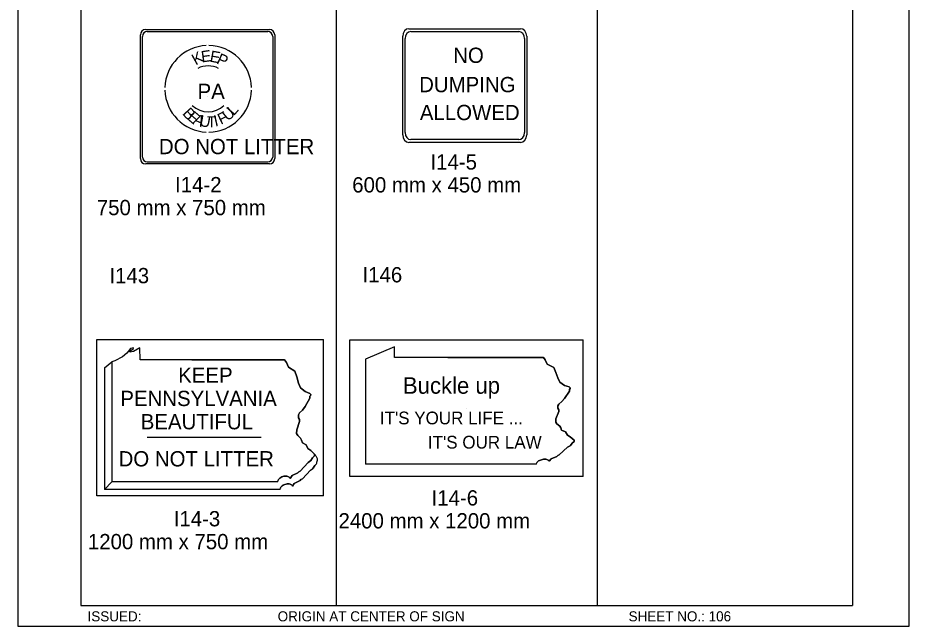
# Model space of a CAD drawing. Extents: x -12 to 6962, y -3756 to 679.
# Drawn here: x 4896 to 5071.3, y -234.4 to -114.9 of the extents above; entities that cross this region are included whole.
import ezdxf

# ---------------------------------------------------------------- set-up
doc = ezdxf.new("R2010")
doc.units = 0
for name, color, linetype in [('Level 1', 7, 'Continuous'), ('Level 2', 7, 'Continuous'), ('Level 3', 7, 'Continuous'), ('Level 61', 7, 'Continuous')]:
    doc.layers.add(name, color=color, linetype=linetype)

msp = doc.modelspace()

# ---------------------------------------------------------------- linework, layer by layer
at = {"layer": 'Level 1'}
for p, q in [((4908.37, -30.35), (4908.37, -230.35)), ((4958.6, -30.35), (4958.6, -230.35)), ((5009.89, -30.35), (5009.89, -230.35)), ((5060.12, -30.35), (5060.12, -230.35)), ((4921.15, -117.2), (4945.45, -117.2)), ((4972.9, -117.04), (4994.85, -117.04)), ((4920.09, -142.56), (4920.09, -118.26)), ((4920.48, -142.25), (4920.48, -118.57)), ((4921.46, -117.6), (4945.13, -117.6)), ((4946.11, -118.57), (4946.11, -142.25)), ((4946.5, -118.26), (4946.5, -142.56)), ((4971.69, -137.91), (4971.69, -118.53)), ((4972.15, -137.46), (4972.15, -118.97)), ((4973.27, -117.6), (4994.49, -117.6)), ((4995.62, -118.97), (4995.62, -137.46)), ((4996.07, -118.53), (4996.07, -137.91)), ((4933.3, -130.41), (4933.3, -130.41)), ((4994.85, -139.4), (4972.9, -139.4)), ((4994.49, -138.84), (4973.27, -138.84)), ((4945.45, -143.62), (4921.15, -143.62)), ((4945.13, -143.23), (4921.46, -143.23)), ((4911.53, -208.85), (4911.53, -178.09)), ((4911.53, -178.09), (4956.07, -178.09)), ((4956.07, -208.85), (4956.07, -178.09)), ((4961.31, -205.05), (4961.31, -178.16)), ((4961.31, -178.16), (5007.18, -178.16)), ((5007.18, -205.05), (5007.18, -178.16)), ((4970.05, -179.57), (4964.38, -181.98)), ((4970.05, -181.67), (4970.05, -179.57)), ((4913.02, -183.66), (4914.51, -182.46)), ((4984.24, -191.61), (4984.24, -191.61)), ((4933.8, -193.47), (4933.8, -193.47)), ((4921.41, -197.28), (4943.85, -197.28)), ((5002.47, -200.77), (5004.1, -199.28)), ((4951.5, -203.96), (4953.08, -202.25)), ((4998, -202.6), (4964.37, -202.6)), ((4998, -202.6), (4964.37, -202.6)), ((4998, -202.6), (4998.03, -202.34)), ((4998, -202.6), (4998.03, -202.34)), ((4998, -202.6), (4998.03, -202.34)), ((4951.94, -205.48), (4953.52, -203.78)), ((5007.18, -205.05), (4961.31, -205.05)), ((4914.51, -206.06), (4913.01, -207.55)), ((4947.15, -206.04), (4914.51, -206.04)), ((4947.15, -206.04), (4914.51, -206.04)), ((4947.15, -206.04), (4947.18, -205.75)), ((4947.15, -206.04), (4947.18, -205.75)), ((4947.15, -206.04), (4947.18, -205.75)), ((4947.6, -207.57), (4913.01, -207.57)), ((4947.6, -207.57), (4914.95, -207.57)), ((4947.6, -207.57), (4914.95, -207.57)), ((4947.6, -207.57), (4947.62, -207.27)), ((4947.6, -207.57), (4947.62, -207.27)), ((4947.6, -207.57), (4947.62, -207.27)), ((4956.07, -208.85), (4911.53, -208.85)), ((4908.37, -230.35), (5060.12, -230.35))]:
    msp.add_line(p, q, dxfattribs=at)
for points in [[(4930.23, -182.1), (4920.02, -182.1), (4920.01, -179.71), (4918.73, -180.43), (4918.01, -180.62), (4918.19, -180.25), (4918.73, -179.88), (4918.74, -179.71), (4918.18, -179.88), (4917.45, -180.79), (4916.55, -181.53), (4915.06, -182.28), (4914.51, -182.46)], [(4953.08, -202.25), (4953.59, -201.9), (4953.97, -201.34), (4954.32, -200.98), (4954.33, -200.63), (4953.58, -199.88), (4953.03, -199.52), (4952.68, -198.8), (4951.94, -198.42), (4951.76, -197.86), (4951.57, -197.5), (4951.03, -196.97), (4950.82, -196.58), (4950.84, -195.86), (4951.39, -194.19), (4951.38, -193.83), (4951.2, -193.47), (4951.21, -192.92), (4951.2, -192.93), (4951.39, -192.54), (4951.95, -191.98), (4952.49, -191.26), (4953.41, -189.61), (4953.4, -189.6), (4953.41, -189.24), (4953.59, -189.06), (4953.59, -188.88), (4953.4, -188.69), (4952.49, -188.33), (4951.57, -187.59), (4951.21, -186.66), (4950.85, -185.43), (4950.47, -184.3), (4949.19, -183.55), (4948.81, -182.63), (4948.45, -182.1), (4930.23, -182.1)], [(4953.08, -202.25), (4953.59, -201.9), (4953.97, -201.34), (4954.32, -200.98), (4954.33, -200.63), (4953.58, -199.88), (4953.03, -199.52), (4952.68, -198.8), (4951.94, -198.42), (4951.76, -197.86), (4951.57, -197.5), (4951.03, -196.97), (4950.82, -196.58), (4950.84, -195.86), (4951.39, -194.19), (4951.38, -193.83), (4951.2, -193.47), (4951.21, -192.92), (4951.2, -192.93), (4951.39, -192.54), (4951.95, -191.98), (4952.49, -191.26), (4953.41, -189.61), (4953.4, -189.6), (4953.41, -189.24), (4953.59, -189.06), (4953.59, -188.88), (4953.4, -188.69), (4952.49, -188.33), (4951.57, -187.59), (4951.21, -186.66), (4950.85, -185.43), (4950.47, -184.3), (4949.19, -183.55), (4948.81, -182.63), (4948.45, -182.1), (4930.23, -182.1)], [(4930.23, -182.1), (4948.45, -182.1), (4948.81, -182.63), (4949.19, -183.55), (4950.47, -184.3), (4950.85, -185.43), (4951.21, -186.66), (4951.57, -187.59), (4952.49, -188.33), (4953.4, -188.69), (4953.59, -188.88), (4953.59, -189.06), (4953.41, -189.24), (4953.4, -189.6), (4953.41, -189.61), (4952.49, -191.26), (4951.95, -191.98), (4951.39, -192.54), (4951.2, -192.93), (4951.21, -192.92), (4951.2, -193.47), (4951.38, -193.83), (4951.39, -194.19), (4950.84, -195.86), (4950.82, -196.58), (4951.03, -196.97), (4951.57, -197.5), (4951.76, -197.86), (4951.94, -198.42), (4952.68, -198.8), (4953.03, -199.52), (4953.58, -199.88), (4954.33, -200.63), (4954.32, -200.98), (4953.97, -201.34), (4953.62, -201.86)], [(4964.38, -181.98), (4964.37, -202.6)], [(5004.1, -199.28), (5004.63, -198.98), (5005.02, -198.49), (5005.38, -198.17), (5005.39, -197.86), (5004.62, -197.21), (5004.05, -196.9), (5003.69, -196.27), (5002.92, -195.93), (5002.74, -195.44), (5002.55, -195.13), (5001.99, -194.67), (5001.78, -194.33), (5001.79, -193.69), (5002.36, -192.24), (5002.35, -191.92), (5002.17, -191.6), (5002.17, -191.13), (5002.17, -191.13), (5002.36, -190.8), (5002.94, -190.31), (5003.5, -189.67), (5004.44, -188.23), (5004.44, -188.22), (5004.44, -187.91), (5004.63, -187.75), (5004.62, -187.6), (5004.43, -187.43), (5003.5, -187.11), (5002.55, -186.47), (5002.17, -185.66), (5001.81, -184.58), (5001.41, -183.59), (5000.09, -182.94), (4999.7, -182.12), (4999.34, -181.66), (4970.05, -181.67)], [(5004.1, -199.28), (5004.63, -198.98), (5005.02, -198.49), (5005.38, -198.17), (5005.39, -197.86), (5004.62, -197.21), (5004.05, -196.9), (5003.69, -196.27), (5002.92, -195.93), (5002.74, -195.44), (5002.55, -195.13), (5001.99, -194.67), (5001.78, -194.33), (5001.79, -193.69), (5002.36, -192.24), (5002.35, -191.92), (5002.17, -191.6), (5002.17, -191.13), (5002.17, -191.13), (5002.36, -190.8), (5002.94, -190.31), (5003.5, -189.67), (5004.44, -188.23), (5004.44, -188.22), (5004.44, -187.91), (5004.63, -187.75), (5004.62, -187.6), (5004.43, -187.43), (5003.5, -187.11), (5002.55, -186.47), (5002.17, -185.66), (5001.81, -184.58), (5001.41, -183.59), (5000.09, -182.94), (4999.7, -182.12), (4999.34, -181.66), (4980.57, -181.67)], [(4980.57, -181.67), (4999.34, -181.66), (4999.7, -182.12), (5000.09, -182.94), (5001.41, -183.59), (5001.81, -184.58), (5002.17, -185.66), (5002.55, -186.47), (5003.5, -187.11), (5004.43, -187.43), (5004.62, -187.6), (5004.63, -187.75), (5004.44, -187.91), (5004.44, -188.22), (5004.44, -188.23), (5003.5, -189.67), (5002.94, -190.31), (5002.36, -190.8), (5002.17, -191.13), (5002.17, -191.13), (5002.17, -191.6), (5002.35, -191.92), (5002.36, -192.24), (5001.79, -193.69), (5001.78, -194.33), (5001.99, -194.67), (5002.55, -195.13), (5002.74, -195.44), (5002.92, -195.93), (5003.69, -196.27), (5004.05, -196.9), (5004.62, -197.21), (5005.39, -197.86), (5005.38, -198.17), (5005.02, -198.49), (5004.65, -198.94)], [(4913.02, -183.66), (4913.01, -207.55)], [(4914.51, -182.46), (4914.51, -206.04)], [(5004.65, -198.94), (5004.63, -198.98), (5004.1, -199.28)], [(4998.02, -202.36), (4998.03, -202.34), (4998.13, -202.2), (4998.24, -202.08), (4998.39, -201.97), (4998.59, -201.86), (4998.76, -201.78), (4998.95, -201.72), (4999.17, -201.67), (4999.39, -201.64), (4999.62, -201.63), (4999.82, -201.64), (5000.01, -201.68), (5000.16, -201.74), (5000.27, -201.8), (5000.39, -201.9), (5000.47, -202.02), (5000.85, -201.55), (5001.99, -201.06), (5002.18, -200.9), (5002.47, -200.77)], [(5002.47, -200.77), (5002.18, -200.9), (5001.99, -201.06), (5000.85, -201.55), (5000.47, -202.02), (5000.39, -201.9), (5000.27, -201.8), (5000.16, -201.74), (5000.01, -201.68), (4999.82, -201.64), (4999.62, -201.63), (4999.39, -201.64), (4999.17, -201.67), (4998.95, -201.72), (4998.76, -201.78), (4998.59, -201.86), (4998.39, -201.97), (4998.24, -202.08), (4998.13, -202.2), (4998.03, -202.34), (4998.02, -202.36)], [(4998.02, -202.36), (4998.03, -202.34), (4998.13, -202.2), (4998.24, -202.08), (4998.39, -201.97), (4998.59, -201.86), (4998.76, -201.78), (4998.95, -201.72), (4999.17, -201.67), (4999.39, -201.64), (4999.62, -201.63), (4999.82, -201.64), (5000.01, -201.68), (5000.16, -201.74), (5000.27, -201.8), (5000.39, -201.9), (5000.47, -202.02), (5000.85, -201.55), (5001.99, -201.06), (5002.18, -200.9), (5002.47, -200.77)], [(4953.62, -201.86), (4953.59, -201.9), (4953.08, -202.25)], [(4953.52, -203.78), (4954.03, -203.42), (4954.41, -202.87), (4954.72, -202.55)], [(4954.4, -202.88), (4954.06, -203.39)], [(4954.58, -202.69), (4954.41, -202.87), (4954.4, -202.88)], [(4954.72, -202.55), (4954.58, -202.69)], [(4947.18, -205.77), (4947.18, -205.75), (4947.28, -205.59), (4947.39, -205.46), (4947.53, -205.33), (4947.73, -205.2), (4947.89, -205.11), (4948.08, -205.04), (4948.29, -204.98), (4948.51, -204.95), (4948.73, -204.94), (4948.92, -204.95), (4949.1, -204.99), (4949.25, -205.06), (4949.36, -205.13), (4949.48, -205.25), (4949.56, -205.39), (4949.92, -204.85), (4951.03, -204.29), (4951.22, -204.1), (4951.5, -203.96)], [(4951.5, -203.96), (4951.22, -204.1), (4951.03, -204.29), (4949.92, -204.85), (4949.56, -205.39), (4949.48, -205.25), (4949.36, -205.13), (4949.25, -205.06), (4949.1, -204.99), (4948.92, -204.95), (4948.73, -204.94), (4948.51, -204.95), (4948.29, -204.98), (4948.08, -205.04), (4947.89, -205.11), (4947.73, -205.2), (4947.53, -205.33), (4947.39, -205.46), (4947.28, -205.59), (4947.18, -205.75), (4947.18, -205.77)], [(4947.18, -205.77), (4947.18, -205.75), (4947.28, -205.59), (4947.39, -205.46), (4947.53, -205.33), (4947.73, -205.2), (4947.89, -205.11), (4948.08, -205.04), (4948.29, -204.98), (4948.51, -204.95), (4948.73, -204.94), (4948.92, -204.95), (4949.1, -204.99), (4949.25, -205.06), (4949.36, -205.13), (4949.48, -205.25), (4949.56, -205.39), (4949.92, -204.85), (4951.03, -204.29), (4951.22, -204.1), (4951.5, -203.96)], [(4947.62, -207.29), (4947.62, -207.27), (4947.72, -207.11), (4947.83, -206.98), (4947.98, -206.85), (4948.17, -206.73), (4948.33, -206.64), (4948.52, -206.57), (4948.74, -206.51), (4948.95, -206.47), (4949.17, -206.47), (4949.37, -206.47), (4949.54, -206.52), (4949.69, -206.59), (4949.8, -206.66), (4949.92, -206.77), (4950, -206.91), (4950.36, -206.37), (4951.48, -205.81), (4951.66, -205.63), (4951.94, -205.48)], [(4951.94, -205.48), (4951.66, -205.63), (4951.48, -205.81), (4950.36, -206.37), (4950, -206.91), (4949.92, -206.77), (4949.8, -206.66), (4949.69, -206.59), (4949.54, -206.52), (4949.37, -206.47), (4949.17, -206.47), (4948.95, -206.47), (4948.74, -206.51), (4948.52, -206.57), (4948.33, -206.64), (4948.17, -206.73), (4947.98, -206.85), (4947.83, -206.98), (4947.72, -207.11), (4947.62, -207.27), (4947.62, -207.29)], [(4947.62, -207.29), (4947.62, -207.27), (4947.72, -207.11), (4947.83, -206.98), (4947.98, -206.85), (4948.17, -206.73), (4948.33, -206.64), (4948.52, -206.57), (4948.74, -206.51), (4948.95, -206.47), (4949.17, -206.47), (4949.37, -206.47), (4949.54, -206.52), (4949.69, -206.59), (4949.8, -206.66), (4949.92, -206.77), (4950, -206.91), (4950.36, -206.37), (4951.48, -205.81), (4951.66, -205.63), (4951.94, -205.48)]]:
    msp.add_lwpolyline(points, dxfattribs=at)
for centre, radius, start, end in [((4921.15, -118.26), 1.06, 90, 180), ((4945.45, -118.26), 1.06, 0, 90), ((4921.46, -118.57), 0.977, 90, 180), ((4945.13, -118.57), 0.977, 0, 90), ((4933.42, -128.85), 8.51, 92.515, 178.3157), ((4933.42, -128.85), 8.51, 1.6843, 89.1462), ((4933.42, -128.85), 4.51, 62.9621, 117.0379), ((4933.42, -128.85), 8.51, 181.6843, 267.485), ((4933.42, -128.85), 8.51, 270.8538, 358.3157), ((4933.42, -128.85), 4.51, 226.3689, 313.6311), ((4921.15, -142.56), 1.06, 180, 270), ((4921.46, -142.25), 0.977, 180, 270), ((4945.13, -142.25), 0.977, 270, 0), ((4945.45, -142.56), 1.06, 270, 0)]:
    msp.add_arc(centre, radius, start, end, dxfattribs=at)
for centre, major_axis, start_param, end_param in [((4972.9, -118.53), (0, -1.49), 3.141593, 4.712389), ((4994.85, -118.53), (0, 1.49), 4.712389, 6.283185), ((4973.27, -118.97), (0, -1.38), 3.141593, 4.712389), ((4994.49, -118.97), (0, 1.38), 4.712389, 6.283185), ((4972.9, -137.91), (0, -1.49), 4.712389, 6.283185), ((4973.27, -137.46), (0, -1.38), 4.712389, 6.283185), ((4994.49, -137.46), (0, 1.38), 3.141593, 4.712389), ((4994.85, -137.91), (0, -1.49), 0, 1.570796)]:
    msp.add_ellipse(centre, major_axis=major_axis, ratio=0.817773, start_param=start_param, end_param=end_param, dxfattribs=at)
msp.add_spline([(4954.72, -202.55), (4954.82, -202.22), (4954.89, -201.84), (4954.89, -201.57), (4954.81, -201.31), (4954.67, -201.06), (4954.33, -200.63)], degree=3, dxfattribs=at)
at = {"layer": 'Level 3'}
msp.add_line((4983.88, -128.22), (4983.88, -128.22), dxfattribs=at)
at = {"layer": 'Level 61'}
msp.add_lwpolyline([(4896, -234.42), (5071.26, -234.42), (5071.26, -21.33), (4896, -21.33)], close=True, dxfattribs=at)

# ---------------------------------------------------------------- texts
at = {"layer": 'Level 1'}
for s, height, p in [('NO', 3, (4981.6, -123.76)), ('PA', 3, (4931.34, -130.85)), ('DUMPING', 3, (4974.91, -129.52)), ('ALLOWED', 3, (4975.05, -135)), ('T', 2.19, (4933.22, -136.42)), ('DO NOT LITTER', 3, (4923.74, -141.69)), ('KEEP', 3, (4927.53, -186.61)), ('Buckle up', 3.25, (4971.72, -188.76)), ('PENNSYLVANIA', 3, (4916.15, -191.18)), ('BEAUTIFUL', 3, (4920.17, -195.75)), ("IT'S YOUR LIFE ...", 2.5, (4967.18, -194.77)), ("IT'S OUR LAW", 2.5, (4976.63, -199.53)), ('DO NOT LITTER', 3, (4915.81, -203.04))]:
    msp.add_text(s, height=height, dxfattribs=at).set_placement(p)
at = {"layer": 'Level 2'}
for s, height, rotation, p in [('K', 2.23, 29.0055, (4930.97, -124.29)), ('E', 2.23, 8.0153, (4932.19, -123.68)), ('E', 2.23, 349.9788, (4933.64, -123.5)), ('P', 2.23, 336.0151, (4934.91, -123.81)), ('B', 2.19, 312.0067, (4928.23, -133.76)), ('E', 2.19, 319.9929, (4929.15, -134.72)), ('U', 2.19, 39.0085, (4937.25, -135.29)), ('L', 2.19, 48.9929, (4938.47, -134.24)), ('A', 2.19, 334.9967, (4930.29, -135.59)), ('U', 2.19, 349.0251, (4931.6, -136.12)), ('I', 2.19, 12.9946, (4934.8, -136.29)), ('F', 2.19, 25.9744, (4935.93, -135.94))]:
    msp.add_text(s, height=height, rotation=rotation, dxfattribs=at).set_placement(p)
for s, p in [('I143', (4914, -167.05)), ('I146', (4963.77, -166.88))]:
    msp.add_text(s, height=3, dxfattribs=at).set_placement(p)
at = {"layer": 'Level 3'}
for s, height, p in [('I14-5', 3, (4977.13, -144.72)), ('I14-2', 3, (4926.91, -149.18)), ('600 mm x 450 mm', 3, (4961.75, -149.22)), ('750 mm x 750 mm', 3, (4911.53, -153.68)), ('I14-6', 3, (4977.35, -210.72)), ('I14-3', 3, (4926.65, -214.81)), ('2400 mm x 1200 mm', 3, (4959.05, -215.22)), ('1200 mm x 750 mm', 3, (4909.77, -219.31)), ('ISSUED:', 1.98, (4909.71, -233.48)), ('ORIGIN AT CENTER OF SIGN', 1.9795, (4947.09, -233.48)), ('SHEET NO.: 106', 1.9795, (5016.09, -233.48))]:
    msp.add_text(s, height=height, dxfattribs=at).set_placement(p)

doc.saveas('drawing.dxf')
